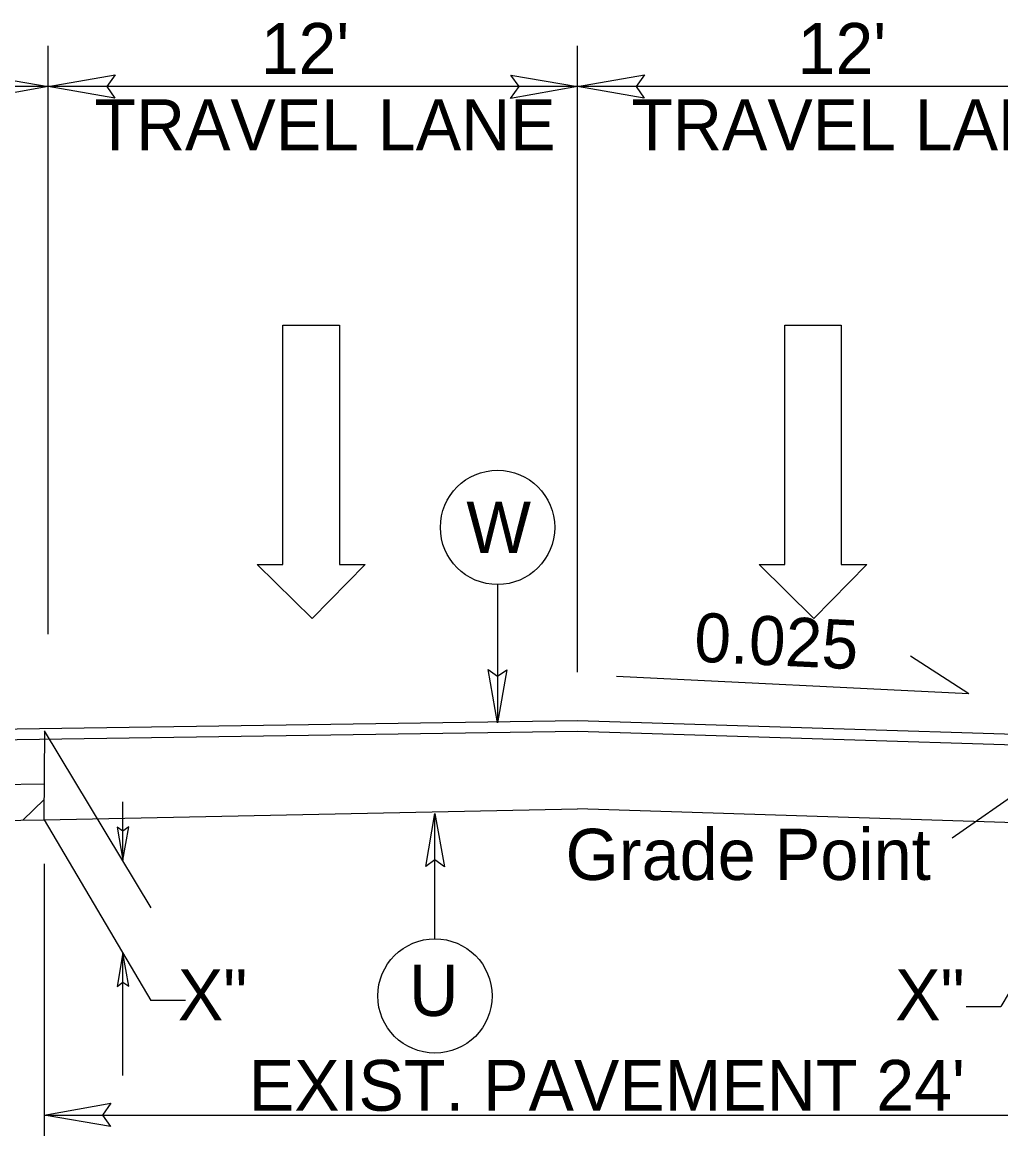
# Model space of a CAD drawing. Extents: x 2176024 to 2177225, y 75947 to 76635.
# Drawn here: x 2176984.66 to 2177006.84, y 76545.94 to 76571.19 of the extents above; entities that cross this region are included whole.
import ezdxf

# ---------------------------------------------------------------- set-up
doc = ezdxf.new("R2010")
doc.units = 0
for name, color, linetype in [('Exist XS Ground Line', 7, 'Continuous'), ('Old_Level_1', 7, 'Continuous'), ('Old_Level_11', 7, 'Continuous'), ('Old_Level_4', 7, 'Continuous'), ('Prop Dimension', 7, 'Continuous'), ('Typical Curb CELL', 7, 'Continuous'), ('Typical Pavement Slope CELL', 7, 'Continuous'), ('Typical Pavement Slope Information CELL', 7, 'Continuous'), ('Typical Slope Point Local CELL', 7, 'Continuous'), ('Typical Terminator CELL', 7, 'Continuous'), ('Typical Text General CELL', 7, 'Continuous')]:
    doc.layers.add(name, color=color, linetype=linetype)

msp = doc.modelspace()

# ---------------------------------------------------------------- linework, layer by layer
at = {"layer": 'Exist XS Ground Line'}
for p in [(2176985.151, 76553.103), (2177009.267, 76552.966)]:
    msp.add_line(p, (2176997.248, 76553.353), dxfattribs=at)
at = {"layer": 'Old_Level_1'}
msp.add_line((2176984.673, 76553.099), (2176985.151, 76553.568), dxfattribs=at)
at = {"layer": 'Old_Level_11'}
for p, q in [((2176995.434, 76558.439), (2176995.434, 76555.306)), ((2177005.742, 76552.698), (2177008.525, 76554.638)), ((2176994.015, 76550.406), (2176994.015, 76553.248))]:
    msp.add_line(p, q, dxfattribs=at)
for points in [[(2176995.641, 76556.506), (2176995.434, 76555.306), (2176995.221, 76556.513), (2176995.434, 76556.36)], [(2176993.808, 76552.048), (2176994.015, 76553.248), (2176994.228, 76552.041), (2176994.015, 76552.195)]]:
    msp.add_lwpolyline(points, close=True, dxfattribs=at)
for centre in [(2176995.434, 76559.735), (2176994.015, 76549.11)]:
    msp.add_circle(centre, 1.296, dxfattribs=at)
at = {"layer": 'Old_Level_4'}
for p, q in [((2176990.569, 76558.891), (2176990.569, 76564.323)), ((2176990.569, 76564.323), (2176991.85, 76564.323)), ((2176991.85, 76564.323), (2176991.85, 76558.891)), ((2177001.944, 76558.891), (2177001.944, 76564.323)), ((2177001.944, 76564.323), (2177003.224, 76564.323)), ((2177003.224, 76564.323), (2177003.224, 76558.891)), ((2176991.229, 76557.669), (2176989.987, 76558.891)), ((2176989.987, 76558.891), (2176990.569, 76558.891)), ((2176992.432, 76558.891), (2176991.229, 76557.669)), ((2176991.85, 76558.891), (2176992.432, 76558.891)), ((2177002.604, 76557.669), (2177001.362, 76558.891)), ((2177001.362, 76558.891), (2177001.944, 76558.891)), ((2177003.806, 76558.891), (2177002.604, 76557.669)), ((2177003.224, 76558.891), (2177003.806, 76558.891))]:
    msp.add_line(p, q, dxfattribs=at)
at = {"layer": 'Prop Dimension'}
for p, q in [((2176985.248, 76557.31), (2176985.248, 76570.656)), ((2176997.248, 76556.455), (2176997.248, 76570.656)), ((2176985.248, 76569.728), (2176973.248, 76569.728)), ((2176997.248, 76569.728), (2176985.248, 76569.728)), ((2177009.248, 76569.728), (2176997.248, 76569.728)), ((2176985.151, 76555.118), (2176987.576, 76551.11)), ((2176986.939, 76552.186), (2176986.939, 76553.514)), ((2176985.151, 76553.103), (2176987.576, 76549.009)), ((2177009.267, 76552.966), (2177006.842, 76548.871)), ((2176985.151, 76552.104), (2176985.151, 76545.94)), ((2176986.939, 76547.308), (2176986.939, 76550.084)), ((2176988.356, 76549.009), (2176987.576, 76549.009)), ((2177006.062, 76548.871), (2177006.842, 76548.871)), ((2176985.151, 76546.409), (2177009.248, 76546.409))]:
    msp.add_line(p, q, dxfattribs=at)
at = {"layer": 'Typical Curb CELL'}
for p, q in [((2176985.151, 76553.103), (2176985.17, 76555.117)), ((2176952.182, 76552.612), (2176985.151, 76553.103))]:
    msp.add_line(p, q, dxfattribs=at)
at = {"layer": 'Typical Pavement Slope CELL'}
msp.add_line((2176985.159, 76553.909), (2176980.689, 76553.843), dxfattribs=at)
at = {"layer": 'Typical Pavement Slope Information CELL'}
for q in [(2177004.799, 76556.814), (2176998.134, 76556.352)]:
    msp.add_line((2177006.118, 76555.964), q, dxfattribs=at)
at = {"layer": 'Typical Slope Point Local CELL'}
msp.add_lwpolyline([(2176969.284, 76554.939), (2176997.248, 76555.355), (2177013.218, 76554.857), (2177013.218, 76554.607), (2176997.248, 76555.105), (2176969.283, 76554.689)], close=True, dxfattribs=at)
at = {"layer": 'Typical Terminator CELL'}
for points in [[(2176983.738, 76569.988), (2176985.248, 76569.728), (2176983.73, 76569.46), (2176983.923, 76569.728)], [(2176986.758, 76569.468), (2176985.248, 76569.728), (2176986.766, 76569.997), (2176986.573, 76569.728)], [(2176995.738, 76569.988), (2176997.248, 76569.728), (2176995.73, 76569.46), (2176995.923, 76569.728)], [(2176998.758, 76569.468), (2176997.248, 76569.728), (2176998.766, 76569.997), (2176998.573, 76569.728)], [(2176986.807, 76552.94), (2176986.939, 76552.186), (2176987.071, 76552.945), (2176986.937, 76552.848)], [(2176987.072, 76549.329), (2176986.939, 76550.084), (2176986.807, 76549.324), (2176986.941, 76549.421)], [(2176986.661, 76546.149), (2176985.151, 76546.409), (2176986.669, 76546.677), (2176986.476, 76546.409)]]:
    msp.add_lwpolyline(points, close=True, dxfattribs=at)

# ---------------------------------------------------------------- texts
at = {"layer": 'Old_Level_11'}
for s, rotation, p in [('W', 0.0003, (2176994.727, 76559.155)), ('Grade Point', 0.0002, (2176996.977, 76551.74)), ('U', 0.0003, (2176993.429, 76548.656))]:
    msp.add_text(s, height=1.16, rotation=rotation, dxfattribs=at).set_placement(p)
for p in [(2176988.186, 76548.559), (2177004.449, 76548.559)]:
    msp.add_text('X"', height=1.1533, dxfattribs=at).set_placement(p)
at = {"layer": 'Typical Pavement Slope Information CELL'}
msp.add_text('0.025', height=1.1106, rotation=357.217, dxfattribs=at).set_placement((2176999.875, 76556.694))
at = {"layer": 'Typical Text General CELL'}
for s, height, p in [("12' ", 1.1533, (2176990.063, 76570.017)), ("12' ", 1.1533, (2177002.237, 76570.017)), ('TRAVEL LANE', 1.15334, (2176986.293, 76568.287)), ('TRAVEL LANE', 1.15334, (2176998.467, 76568.287)), ("EXIST. PAVEMENT 24'", 1.15334, (2176989.795, 76546.506))]:
    msp.add_text(s, height=height, dxfattribs=at).set_placement(p)

doc.saveas('drawing.dxf')
